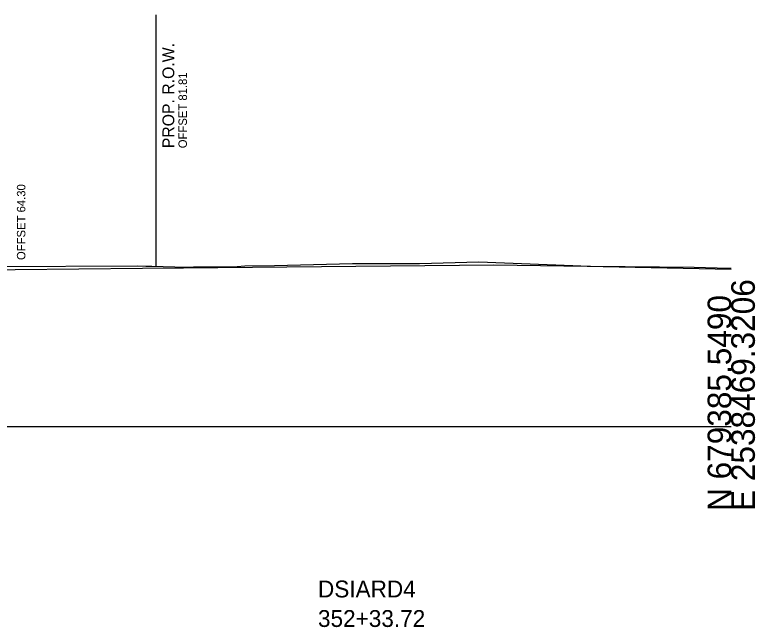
# Model space of a CAD drawing. Extents: x -26 to 1603, y -30 to 14537.
# Drawn here: x 1515.1 to 1602.8, y 1476.2 to 1548.8 of the extents above; entities that cross this region are included whole.
import ezdxf

# ---------------------------------------------------------------- set-up
doc = ezdxf.new("R2010")
doc.units = 0
for name, color, linetype in [('DESIGN - ROW - Right-of-Way and Easement Labels', 7, 'Continuous'), ('DESIGN - ROW - Right-of-Way Linework', 7, 'Continuous'), ('DESIGN - SHEET - Light Grid', 7, 'Continuous'), ('DESIGN - TYPICAL - Slope Tie Text', 7, 'Continuous'), ('DESIGN - TYPICAL - Warning Text', 7, 'Continuous'), ('SURVEY - GROUND - Top of Ground', 7, 'Continuous')]:
    doc.layers.add(name, color=color, linetype=linetype)

msp = doc.modelspace()

# ---------------------------------------------------------------- linework, layer by layer
at = {"layer": 'DESIGN - ROW - Right-of-Way Linework'}
msp.add_line((1531.81, 1519.008), (1531.81, 1548.832), dxfattribs=at)
at = {"layer": 'DESIGN - SHEET - Light Grid'}
msp.add_line((1450, 1500), (1600, 1500), dxfattribs=at)
at = {"layer": 'SURVEY - GROUND - Top of Ground'}
for points in [[(1300, 1500.952), (1309.354, 1501.306), (1361.065, 1500.999), (1365.868, 1500.972), (1366.398, 1500.98), (1417.725, 1513.447), (1428.154, 1516.233), (1433.778, 1516.444), (1450, 1517.048), (1476.94, 1518.051), (1483.45, 1518.172), (1485.252, 1518.195), (1499.967, 1518.472), (1530.191, 1518.785), (1535.054, 1518.842), (1571.835, 1519.188), (1582.907, 1519.011), (1600, 1518.681)], [(1512.501, 1518.996), (1529.643, 1519.072), (1530.601, 1519.032), (1531.31, 1519.021), (1535.382, 1518.922), (1536.235, 1518.93), (1541.431, 1519.001), (1542.322, 1519.057), (1545.858, 1519.109), (1555.096, 1519.34), (1563.047, 1519.329), (1570.066, 1519.524), (1581.232, 1519.09), (1582.173, 1519.049), (1583.316, 1519.031), (1595.611, 1518.91), (1599.683, 1518.795), (1600, 1518.789)]]:
    msp.add_lwpolyline(points, dxfattribs=at)

# ---------------------------------------------------------------- texts
at = {"layer": 'DESIGN - ROW - Right-of-Way and Easement Labels'}
for s, height, p in [('PROP. R.O.W.', 1.4, (1533.96, 1533.01)), ('OFFSET 81.81', 1, (1535.46, 1533.01))]:
    msp.add_text(s, height=height, rotation=90, dxfattribs=at).set_placement(p)
at = {"layer": 'DESIGN - SHEET - Light Grid'}
for s, p in [('E 2538469.3206', (1602.8, 1490)), ('N 679385.5490', (1600, 1490))]:
    msp.add_text(s, height=2.8, rotation=90, dxfattribs=at).set_placement(p)
at = {"layer": 'DESIGN - TYPICAL - Slope Tie Text'}
msp.add_text('OFFSET 64.30', height=1, rotation=90, dxfattribs=at).set_placement((1516.303, 1519.754))
at = {"layer": 'DESIGN - TYPICAL - Warning Text'}
for s, p in [('DSIARD4', (1551, 1479.75)), ('352+33.72', (1551, 1476.25))]:
    msp.add_text(s, height=2, dxfattribs=at).set_placement(p)

doc.saveas('drawing.dxf')
